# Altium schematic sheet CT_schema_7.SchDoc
size 277 x 170 mm
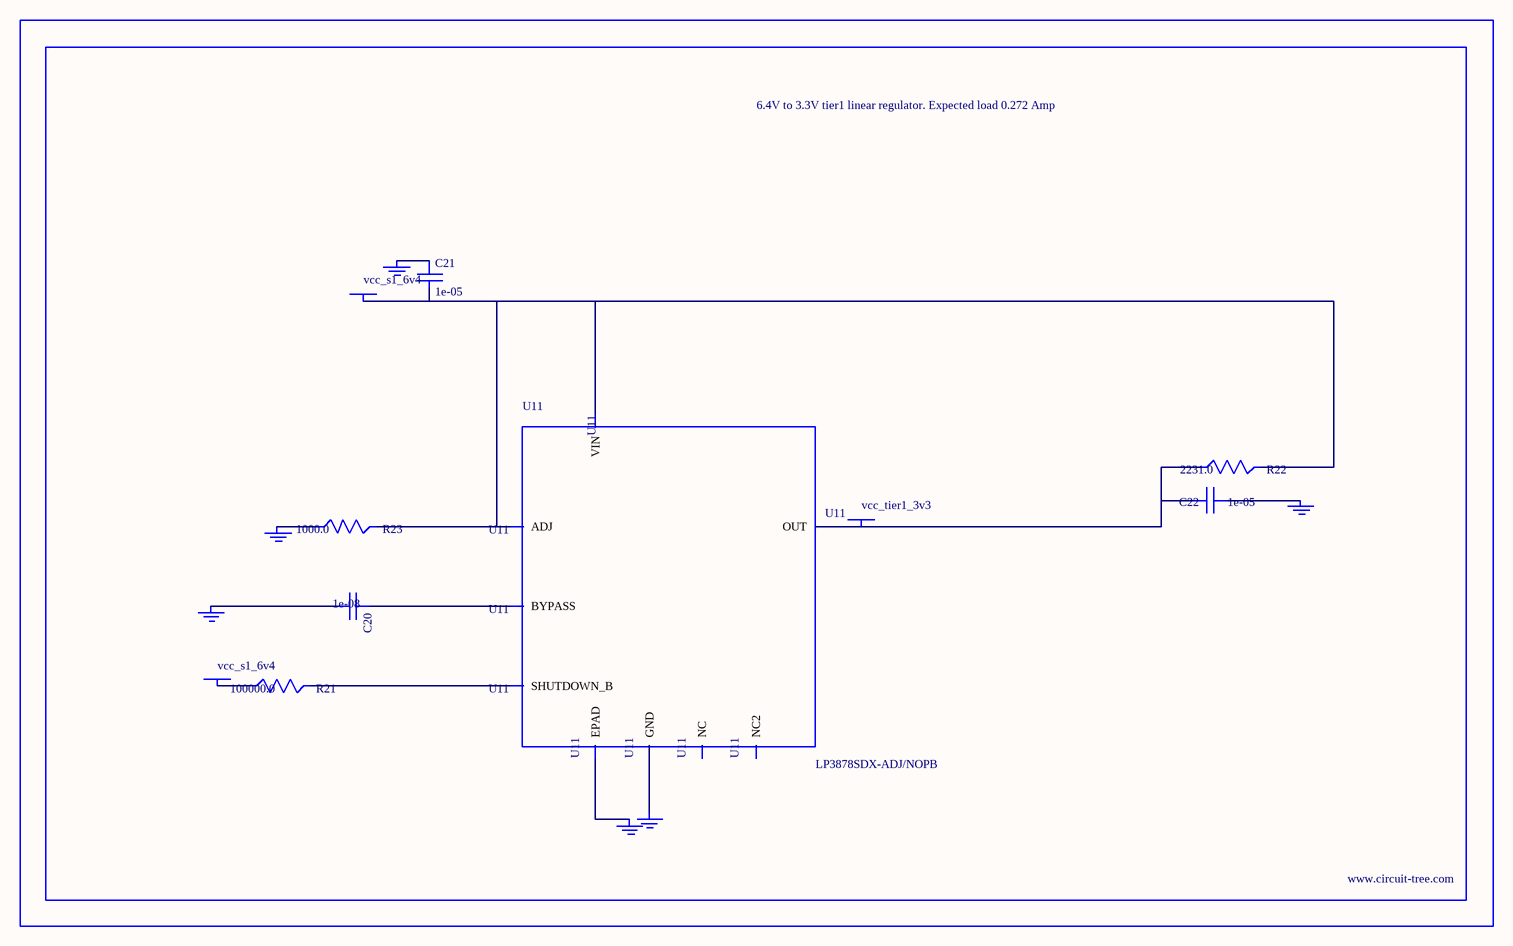
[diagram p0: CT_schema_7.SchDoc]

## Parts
BORDER6  (no value)
C20  1e-08  [C0402]
C21  1e-05  [C1206]
C22  1e-05  [C1210]
GND_INSTANCE_6_0  (no value)
GND_INSTANCE_6_1  (no value)
GND_INSTANCE_6_2  (no value)
GND_INSTANCE_6_3  (no value)
GND_INSTANCE_6_4  (no value)
GND_INSTANCE_6_5  (no value)
POWER_INSTANCE_6_0  vcc_s1_6v4
POWER_INSTANCE_6_1  vcc_s1_6v4
POWER_INSTANCE_6_2  vcc_tier1_3v3
R21  100000.0  [R0603]
R22  2231.0  [R0603]
R23  1000.0  [R0603]
U11  LP3878SDX-ADJ/NOPB  [WSON-8]

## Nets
NetC20_1: C20.1 U11.1(BYPASS)
NetC20_2: C20.2 GND_INSTANCE_6_0.0(GND)
NetC21_1: C21.1 GND_INSTANCE_6_1.0(GND)
NetC21_2: C21.2 POWER_INSTANCE_6_0.0(PWR) R22.2 R23.2 U11.4(VIN) U11.6(ADJ)
NetC22_1: C22.1 GND_INSTANCE_6_2.0(GND)
NetC22_2: C22.2 POWER_INSTANCE_6_2.0(PWR) R22.1 U11.5(OUT)
NetGND_INSTANCE_6_3_0: GND_INSTANCE_6_3.0(GND) R23.1
NetGND_INSTANCE_6_4_0: GND_INSTANCE_6_4.0(GND) U11.PAD(EPAD)
NetGND_INSTANCE_6_5_0: GND_INSTANCE_6_5.0(GND) U11.3(GND)
NetPOWER_INSTANCE_6_1_0: POWER_INSTANCE_6_1.0(PWR) R21.1
NetR21_2: R21.2 U11.8(SHUTDOWN_B)

Not connected (* = marked no-connect by the designer): U11 2(NC) 7(NC2)

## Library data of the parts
BORDER6 = BORDER_PAGE6
C20 = C0402C103K3RAC
C21 = C1206C106K3RACTU
C22 = GRM32DR61E106MA12L
GND_INSTANCE_6_0-GND_INSTANCE_6_5 = GND
POWER_INSTANCE_6_0-POWER_INSTANCE_6_2 = PWR
R21 = RC0603JR-07100KL
R22 = R22
R23 = RC0603JR-071KL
